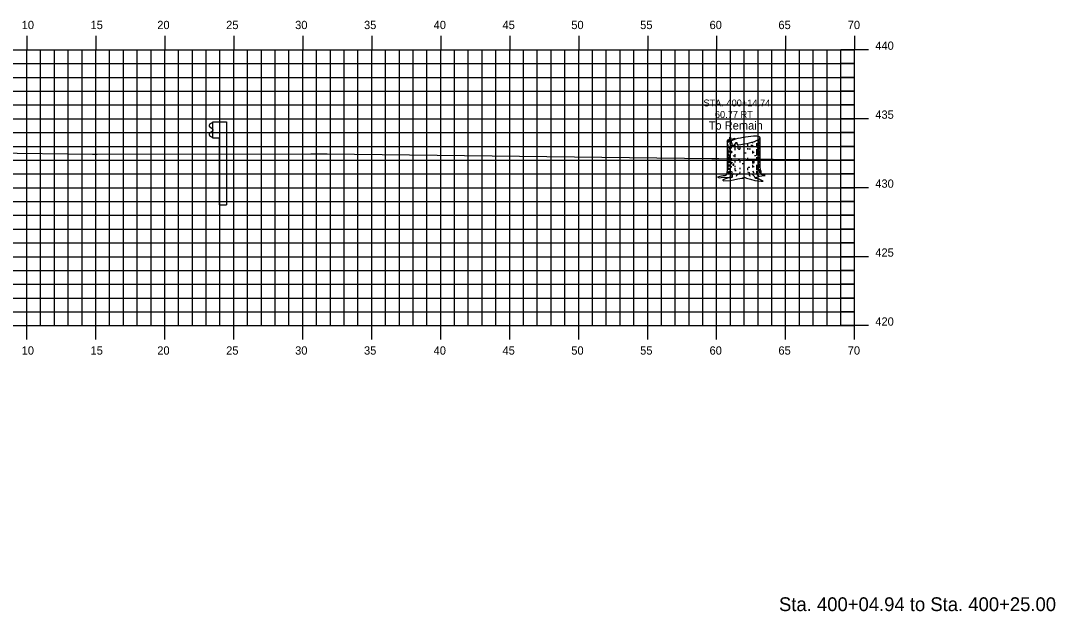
# Model space of a CAD drawing. Extents: x -161 to 764, y 111 to 210.
# Drawn here: x -78.3 to -3.3, y 113.1 to 155.9 of the extents above; entities that cross this region are included whole.
import ezdxf

# ---------------------------------------------------------------- set-up
doc = ezdxf.new("R2010")
doc.units = 0
for name, color, linetype in [('D_Text_Monospaced', 7, 'Continuous'), ('D_Text_Standard', 7, 'Continuous'), ('H_V ANNOTATION', 7, 'Continuous'), ('MAJOR', 7, 'Continuous'), ('MINOR', 7, 'Continuous'), ('S_Guardrail_Beam', 7, 'Continuous'), ('S_Roadway_Centerline', 7, 'Continuous'), ('S_Trees_Decid_Pay', 7, 'Continuous')]:
    doc.layers.add(name, color=color, linetype=linetype)

msp = doc.modelspace()

# ---------------------------------------------------------------- linework, layer by layer
at = {"layer": 'MAJOR'}
for p, q in [((-77.863, 154.77), (-77.863, 153.768)), ((-72.863, 154.77), (-72.863, 153.768)), ((-67.863, 154.77), (-67.863, 153.768)), ((-62.863, 154.77), (-62.863, 153.768)), ((-57.863, 154.77), (-57.863, 153.768)), ((-52.863, 154.77), (-52.863, 153.768)), ((-47.863, 154.77), (-47.863, 153.768)), ((-42.863, 154.77), (-42.863, 153.768)), ((-37.863, 154.77), (-37.863, 153.768)), ((-32.863, 154.77), (-32.863, 153.768)), ((-27.863, 154.77), (-27.863, 153.768)), ((-22.863, 154.77), (-22.863, 153.768)), ((-17.863, 154.77), (-17.863, 153.768)), ((-157.863, 153.768), (-17.863, 153.768)), ((-157.863, 153.768), (-17.863, 153.768)), ((-77.863, 133.768), (-77.863, 153.768)), ((-72.863, 133.768), (-72.863, 153.768)), ((-67.863, 133.768), (-67.863, 153.768)), ((-62.863, 133.768), (-62.863, 153.768)), ((-57.863, 133.768), (-57.863, 153.768)), ((-52.863, 133.768), (-52.863, 153.768)), ((-47.863, 133.768), (-47.863, 153.768)), ((-42.863, 133.768), (-42.863, 153.768)), ((-37.863, 133.768), (-37.863, 153.768)), ((-32.863, 133.768), (-32.863, 153.768)), ((-27.863, 133.768), (-27.863, 153.768)), ((-22.863, 133.768), (-22.863, 153.768)), ((-16.861, 153.768), (-18.865, 153.768)), ((-17.863, 133.768), (-17.863, 153.768)), ((-17.863, 133.768), (-17.863, 153.768)), ((-157.863, 148.768), (-17.863, 148.768)), ((-16.861, 148.768), (-18.865, 148.768)), ((-157.863, 143.768), (-17.863, 143.768)), ((-16.861, 143.768), (-18.865, 143.768)), ((-157.863, 138.768), (-17.863, 138.768)), ((-16.861, 138.768), (-18.865, 138.768)), ((-157.863, 133.768), (-17.863, 133.768)), ((-157.863, 133.768), (-17.863, 133.768)), ((-77.863, 132.766), (-77.863, 133.768)), ((-72.863, 132.766), (-72.863, 133.768)), ((-67.863, 132.766), (-67.863, 133.768)), ((-62.863, 132.766), (-62.863, 133.768)), ((-57.863, 132.766), (-57.863, 133.768)), ((-52.863, 132.766), (-52.863, 133.768)), ((-47.863, 132.766), (-47.863, 133.768)), ((-42.863, 132.766), (-42.863, 133.768)), ((-37.863, 132.766), (-37.863, 133.768)), ((-32.863, 132.766), (-32.863, 133.768)), ((-27.863, 132.766), (-27.863, 133.768)), ((-22.863, 132.766), (-22.863, 133.768)), ((-16.861, 133.768), (-18.865, 133.768)), ((-17.863, 132.766), (-17.863, 133.768))]:
    msp.add_line(p, q, dxfattribs=at)
at = {"layer": 'MINOR'}
for p, q in [((-76.863, 133.768), (-76.863, 153.768)), ((-75.863, 133.768), (-75.863, 153.768)), ((-74.863, 133.768), (-74.863, 153.768)), ((-73.863, 133.768), (-73.863, 153.768)), ((-71.863, 133.768), (-71.863, 153.768)), ((-70.863, 133.768), (-70.863, 153.768)), ((-69.863, 133.768), (-69.863, 153.768)), ((-68.863, 133.768), (-68.863, 153.768)), ((-66.863, 133.768), (-66.863, 153.768)), ((-65.863, 133.768), (-65.863, 153.768)), ((-64.863, 133.768), (-64.863, 153.768)), ((-63.863, 133.768), (-63.863, 153.768)), ((-61.863, 133.768), (-61.863, 153.768)), ((-60.863, 133.768), (-60.863, 153.768)), ((-59.863, 133.768), (-59.863, 153.768)), ((-58.863, 133.768), (-58.863, 153.768)), ((-56.863, 133.768), (-56.863, 153.768)), ((-55.863, 133.768), (-55.863, 153.768)), ((-54.863, 133.768), (-54.863, 153.768)), ((-53.863, 133.768), (-53.863, 153.768)), ((-51.863, 133.768), (-51.863, 153.768)), ((-50.863, 133.768), (-50.863, 153.768)), ((-49.863, 133.768), (-49.863, 153.768)), ((-48.863, 133.768), (-48.863, 153.768)), ((-46.863, 133.768), (-46.863, 153.768)), ((-45.863, 133.768), (-45.863, 153.768)), ((-44.863, 133.768), (-44.863, 153.768)), ((-43.863, 133.768), (-43.863, 153.768)), ((-41.863, 133.768), (-41.863, 153.768)), ((-40.863, 133.768), (-40.863, 153.768)), ((-39.863, 133.768), (-39.863, 153.768)), ((-38.863, 133.768), (-38.863, 153.768)), ((-36.863, 133.768), (-36.863, 153.768)), ((-35.863, 133.768), (-35.863, 153.768)), ((-34.863, 133.768), (-34.863, 153.768)), ((-33.863, 133.768), (-33.863, 153.768)), ((-31.863, 133.768), (-31.863, 153.768)), ((-30.863, 133.768), (-30.863, 153.768)), ((-29.863, 133.768), (-29.863, 153.768)), ((-28.863, 133.768), (-28.863, 153.768)), ((-26.863, 133.768), (-26.863, 153.768)), ((-25.863, 133.768), (-25.863, 153.768)), ((-24.863, 133.768), (-24.863, 153.768)), ((-23.863, 133.768), (-23.863, 153.768)), ((-21.863, 133.768), (-21.863, 153.768)), ((-20.863, 133.768), (-20.863, 153.768)), ((-19.863, 133.768), (-19.863, 153.768)), ((-18.863, 133.768), (-18.863, 153.768)), ((-157.863, 152.768), (-17.863, 152.768)), ((-17.863, 152.768), (-18.865, 152.768)), ((-157.863, 151.768), (-17.863, 151.768)), ((-17.863, 151.768), (-18.865, 151.768)), ((-157.863, 150.768), (-17.863, 150.768)), ((-17.863, 150.768), (-18.865, 150.768)), ((-157.863, 149.768), (-17.863, 149.768)), ((-17.863, 149.768), (-18.865, 149.768)), ((-157.863, 147.768), (-17.863, 147.768)), ((-17.863, 147.768), (-18.865, 147.768)), ((-157.863, 146.768), (-17.863, 146.768)), ((-17.863, 146.768), (-18.865, 146.768)), ((-157.863, 145.768), (-17.863, 145.768)), ((-17.863, 145.768), (-18.865, 145.768)), ((-157.863, 144.768), (-17.863, 144.768)), ((-17.863, 144.768), (-18.865, 144.768)), ((-157.863, 142.768), (-17.863, 142.768)), ((-17.863, 142.768), (-18.865, 142.768)), ((-157.863, 141.768), (-17.863, 141.768)), ((-17.863, 141.768), (-18.865, 141.768)), ((-157.863, 140.768), (-17.863, 140.768)), ((-17.863, 140.768), (-18.865, 140.768)), ((-157.863, 139.768), (-17.863, 139.768)), ((-17.863, 139.768), (-18.865, 139.768)), ((-157.863, 137.768), (-17.863, 137.768)), ((-17.863, 137.768), (-18.865, 137.768)), ((-157.863, 136.768), (-17.863, 136.768)), ((-17.863, 136.768), (-18.865, 136.768)), ((-157.863, 135.768), (-17.863, 135.768)), ((-17.863, 135.768), (-18.865, 135.768)), ((-157.863, 134.768), (-17.863, 134.768)), ((-17.863, 134.768), (-18.865, 134.768))]:
    msp.add_line(p, q, dxfattribs=at)
at = {"layer": 'S_Guardrail_Beam'}
for p, q in [((-64.38, 148.534), (-63.891, 148.534)), ((-64.38, 147.368), (-64.38, 148.534)), ((-63.891, 148.534), (-63.399, 148.534)), ((-63.891, 148.534), (-63.891, 147.368)), ((-63.399, 148.534), (-63.399, 142.534)), ((-64.479, 148.44), (-64.622, 148.34)), ((-64.622, 148.197), (-64.427, 148.061)), ((-64.427, 147.841), (-64.622, 147.705)), ((-64.38, 148.462), (-64.462, 148.447)), ((-64.393, 147.997), (-64.393, 147.906)), ((-64.622, 147.562), (-64.479, 147.462)), ((-64.462, 147.455), (-64.38, 147.441)), ((-63.891, 147.368), (-64.38, 147.368)), ((-63.891, 142.534), (-63.891, 147.368)), ((-63.891, 142.534), (-63.399, 142.534))]:
    msp.add_line(p, q, dxfattribs=at)
for centre, major_axis, start_param, end_param in [((-64.572, 148.269), (-0.0877, 0), 5.323254, 7.243116), ((-64.455, 148.406), (-0.0417, 0), 4.886922, 5.323254), ((-64.472, 147.997), (0.0789, 0), 0, 0.959931), ((-64.472, 147.906), (0.0789, 0), 5.323254, 6.283185), ((-64.572, 147.633), (-0.0877, 0), 5.323254, 7.243116), ((-64.455, 147.496), (-0.0417, 0), 0.959931, 1.396263)]:
    msp.add_ellipse(centre, major_axis=major_axis, ratio=0.995501, start_param=start_param, end_param=end_param, dxfattribs=at)
at = {"layer": 'S_Roadway_Centerline'}
msp.add_lwpolyline([(-80.412, 146.295), (-73.107, 146.205), (-72.997, 146.194), (-72.768, 146.204), (-57.278, 146.215), (-56.524, 146.221), (-56.324, 146.222), (-56.096, 146.218), (-28.215, 145.898), (-27.887, 145.887), (-27.711, 145.882), (-17.863, 145.764)], dxfattribs=at)
at = {"layer": 'S_Trees_Decid_Pay'}
for p, q in [((-26.896, 147.097), (-26.896, 146.923)), ((-25.639, 146.988), (-25.639, 146.708)), ((-25.256, 147.09), (-25.256, 147.003)), ((-24.983, 147.003), (-24.983, 146.811)), ((-24.851, 147.256), (-24.851, 147.003)), ((-24.771, 147.301), (-24.771, 147.18)), ((-24.771, 147.128), (-24.771, 146.914)), ((-27.045, 146.897), (-27.045, 146.643)), ((-27.045, 146.546), (-27.045, 146.076)), ((-26.959, 146.752), (-26.959, 146.54)), ((-26.959, 146.474), (-26.959, 146.326)), ((-26.811, 146.849), (-26.811, 146.644)), ((-26.811, 146.437), (-26.811, 146.282)), ((-26.55, 146.851), (-26.55, 146.731)), ((-26.55, 146.679), (-26.55, 146.494)), ((-26.312, 146.579), (-26.306, 146.686)), ((-26.185, 146.752), (-26.185, 146.572)), ((-25.639, 146.643), (-25.639, 146.54)), ((-25.256, 146.862), (-25.256, 146.723)), ((-25.256, 146.437), (-25.256, 146.245)), ((-24.983, 146.56), (-24.983, 146.282)), ((-24.851, 146.906), (-24.851, 146.643)), ((-24.851, 146.546), (-24.851, 146.237)), ((-24.771, 146.869), (-24.771, 146.531)), ((-24.771, 146.414), (-24.771, 146.053)), ((-27.045, 146.025), (-27.045, 145.891)), ((-27.045, 145.834), (-27.045, 145.508)), ((-26.959, 146.149), (-26.959, 145.848)), ((-26.959, 145.811), (-26.959, 145.568)), ((-26.811, 145.92), (-26.811, 145.7)), ((-26.811, 145.6), (-26.811, 145.479)), ((-26.55, 146.208), (-26.55, 145.98)), ((-26.55, 145.782), (-26.55, 145.597)), ((-26.185, 145.794), (-26.185, 145.597)), ((-25.639, 145.928), (-25.639, 145.708)), ((-25.256, 145.765), (-25.256, 145.557)), ((-24.983, 146.237), (-24.983, 146.128)), ((-24.983, 145.994), (-24.983, 145.765)), ((-24.851, 146.149), (-24.851, 146.082)), ((-24.851, 145.848), (-24.851, 145.751)), ((-24.851, 145.7), (-24.851, 145.34)), ((-24.771, 146.017), (-24.771, 145.568)), ((-24.771, 145.502), (-24.771, 145.22)), ((-27.042, 144.956), (-27.056, 144.839)), ((-27.045, 145.479), (-27.045, 145.059)), ((-26.959, 145.457), (-26.959, 145.317)), ((-26.959, 145.185), (-26.959, 145.029)), ((-26.811, 145.328), (-26.811, 145.23)), ((-26.55, 145.362), (-26.55, 145.285)), ((-26.55, 145.208), (-26.55, 145.034)), ((-26.185, 145.214), (-26.185, 145.111)), ((-25.639, 145.208), (-25.639, 145.034)), ((-25.26, 144.979), (-25.18, 144.847)), ((-25.256, 145.436), (-25.256, 145.237)), ((-24.983, 145.436), (-24.983, 145.053)), ((-24.851, 145.288), (-24.851, 145.121))]:
    msp.add_line(p, q, dxfattribs=at)
for points in [[(-27.096, 147.172), (-27.096, 145.034), (-27.116, 144.893), (-27.122, 144.767), (-27.165, 144.68), (-27.258, 144.631), (-27.394, 144.631), (-27.637, 144.575), (-27.804, 144.526), (-27.661, 144.495), (-27.424, 144.532), (-27.214, 144.52), (-26.953, 144.526), (-26.829, 144.544), (-26.799, 144.502), (-26.737, 144.544), (-26.836, 144.477), (-27.071, 144.452), (-27.301, 144.39), (-27.431, 144.32), (-27.332, 144.277), (-26.91, 144.296), (-26.632, 144.339), (-26.333, 144.415), (-26.047, 144.452), (-25.942, 144.452), (-25.924, 144.532), (-25.855, 144.538), (-25.689, 144.452), (-25.403, 144.396), (-25.104, 144.289), (-24.645, 144.24), (-24.491, 144.252), (-24.833, 144.403), (-25.036, 144.433), (-25.024, 144.508), (-24.764, 144.607), (-24.589, 144.637), (-24.348, 144.649), (-24.546, 144.687), (-24.608, 144.723), (-24.632, 144.81), (-24.645, 144.979), (-24.69, 145.065), (-24.718, 145.306), (-24.718, 147.392)], [(-26.739, 146.844), (-26.747, 146.988), (-26.792, 146.981), (-26.807, 147.355), (-26.901, 147.363), (-26.916, 147.443), (-26.953, 147.106), (-26.999, 147.2), (-27.019, 147.046), (-27.096, 147.172), (-27.09, 146.982)], [(-27.096, 147.172), (-27.05, 147.195), (-27.027, 147.26), (-26.976, 147.283), (-26.942, 147.208)], [(-26.717, 147.21), (-26.696, 147.318), (-26.564, 147.349), (-26.557, 147.261)], [(-26.578, 146.849), (-26.541, 146.952), (-26.476, 146.958), (-26.476, 147.04), (-26.401, 147.046), (-26.376, 146.866)], [(-26.688, 145.479), (-26.696, 145.405), (-26.622, 145.399), (-26.607, 145.516)], [(-25.142, 145.571), (-25.144, 145.648), (-25.151, 145.714)], [(-26.976, 144.964), (-26.982, 144.839), (-27.064, 144.744)], [(-26.829, 144.544), (-26.811, 144.723), (-26.749, 144.86), (-26.756, 144.96)], [(-26.638, 144.792), (-26.712, 144.723), (-26.731, 144.625), (-26.737, 144.544)], [(-26.187, 144.927), (-26.204, 144.773), (-26.401, 144.693), (-26.447, 144.59)], [(-25.621, 144.919), (-25.518, 144.868), (-25.504, 144.662), (-25.401, 144.633)], [(-24.966, 144.993), (-24.966, 144.788), (-24.909, 144.678), (-24.812, 144.662)], [(-24.826, 145.067), (-24.754, 144.964), (-24.754, 144.839)], [(-24.769, 145.148), (-24.709, 144.987), (-24.695, 144.862), (-24.703, 144.765)], [(-25.036, 144.433), (-25.123, 144.575), (-25.254, 144.717)]]:
    msp.add_lwpolyline(points, dxfattribs=at)
for centre, radius, start, end in [((-26.286, 145.984), 1.299, 107.86134, 113.3069), ((-24.806, 141.391), 6.126, 100.77788, 107.86134), ((-24.806, 141.391), 6.126, 93.69441, 100.77788), ((-27.008, 152.959), 6.126, 280.77788, 287.86134), ((-25.117, 146.207), 1.299, 78.27788, 93.69441), ((-25.528, 148.365), 1.299, 287.86134, 303.27788), ((-24.95, 147.01), 0.48, 69.98432, 78.27788), ((-25.078, 147.68), 0.48, 303.27788, 311.57144), ((-24.842, 147.306), 0.164, 55.77788, 69.98432), ((-24.858, 147.135), 0.166, 301.67004, 315), ((-24.868, 147.444), 0.164, 311.57144, 325.77788), ((-24.81, 147.353), 0.107, 45.9547, 55.77788), ((-24.817, 147.095), 0.109, 315, 324.82628), ((-24.78, 147.384), 0.0645, 33.27788, 45.9547), ((-24.821, 147.412), 0.107, 325.77788, 335.60106), ((-24.782, 147.07), 0.0657, 324.82628, 337.5), ((-24.772, 147.389), 0.0544, 22.46002, 33.27788), ((-24.782, 147.394), 0.0645, 335.60106, 348.27788), ((-24.765, 147.392), 0.0467, 10.77788, 22.46002), ((-24.772, 147.066), 0.0554, 337.5, 348.31854), ((-24.765, 147.392), 0.0467, 359.09574, 10.77788), ((-24.773, 147.392), 0.0544, 348.27788, 359.09574), ((-27.048, 146.803), 0.0476, 180, 191.68146), ((-27.048, 146.282), 0.0476, 180, 191.68146), ((-27.04, 146.805), 0.0554, 191.68146, 202.5), ((-27.04, 146.284), 0.0554, 191.68146, 202.5), ((-27.031, 146.809), 0.0657, 202.5, 215.17372), ((-27.031, 146.288), 0.0657, 202.5, 215.17372), ((-26.995, 146.834), 0.109, 215.17372, 225), ((-26.995, 146.313), 0.109, 215.17372, 225), ((-26.955, 146.874), 0.166, 225, 239.19244), ((-26.955, 146.611), 0.166, 237.03779, 239.19244), ((-26.792, 146.884), 0.484, 239.19244, 247.5), ((-26.483, 147.63), 1.292, 247.5, 248.35373), ((-26.483, 147.894), 1.292, 250.61187, 255.28558), ((-26.483, 147.63), 1.292, 255.28558, 259.26323), ((-26.697, 148.143), 1.299, 268.12894, 273.69441), ((-27.008, 152.959), 6.126, 273.69441, 274.02462), ((-27.008, 152.959), 6.126, 275.91473, 280.77788), ((-25.907, 152.481), 5.916, 266.07764, 267.30434), ((-25.907, 152.218), 5.916, 270.1162, 271.77083), ((-25.907, 152.481), 5.916, 273.53821, 274.89239), ((-25.906, 152.742), 5.916, 274.95145, 276.30875), ((-25.907, 152.218), 5.916, 276.31835, 277.15463), ((-25.331, 147.63), 1.292, 277.15463, 278.36619), ((-25.33, 148.154), 1.292, 285.56513, 289.09156), ((-25.331, 147.894), 1.292, 288.08294, 292.5), ((-25.331, 147.63), 1.292, 291.8071, 292.5), ((-25.022, 146.884), 0.484, 292.5, 300.80756), ((-25.022, 147.147), 0.484, 297.41617, 300.80756), ((-24.859, 146.874), 0.166, 300.80756, 315), ((-24.859, 146.611), 0.166, 300.80756, 301.6001), ((-24.818, 146.834), 0.109, 315, 324.82628), ((-24.818, 146.313), 0.109, 315, 324.82628), ((-24.783, 146.809), 0.0657, 324.82628, 337.5), ((-24.783, 146.288), 0.0657, 324.82628, 337.5), ((-24.773, 146.805), 0.0554, 337.5, 348.31854), ((-24.773, 146.284), 0.0554, 337.5, 348.31854), ((-27.048, 146.025), 0.0476, 180, 191.68146), ((-27.048, 145.759), 0.0476, 180, 191.68146), ((-27.04, 146.026), 0.0554, 191.68146, 202.5), ((-27.04, 145.761), 0.0554, 191.68146, 202.5), ((-27.031, 146.03), 0.0657, 202.5, 215.17372), ((-27.031, 145.765), 0.0657, 202.5, 215.17372), ((-26.995, 146.055), 0.109, 215.17372, 225), ((-26.995, 145.79), 0.109, 215.17372, 225), ((-26.955, 146.353), 0.166, 225, 239.19244), ((-26.955, 146.096), 0.166, 225, 239.19244), ((-26.955, 145.83), 0.166, 225, 239.19244), ((-26.792, 146.626), 0.484, 239.19244, 245.77245), ((-26.792, 146.103), 0.484, 239.19244, 247.5), ((-26.483, 147.373), 1.292, 247.5, 248.48417), ((-26.483, 147.115), 1.292, 247.5, 251.79898), ((-26.483, 146.85), 1.292, 247.5, 248.35373), ((-26.483, 146.85), 1.292, 255.28558, 259.24628), ((-26.483, 147.373), 1.292, 261.87258, 262.84538), ((-25.907, 151.961), 5.916, 262.84538, 263.7595), ((-25.907, 151.703), 5.916, 266.27211, 267.30434), ((-25.907, 151.438), 5.916, 268.92065, 270), ((-25.907, 151.438), 5.916, 270, 270.27568), ((-25.907, 151.438), 5.916, 276.31835, 277.15463), ((-25.331, 146.85), 1.292, 277.15463, 278.37952), ((-25.331, 147.373), 1.292, 279.25654, 285.6105), ((-25.331, 147.115), 1.292, 285.61049, 290.10015), ((-25.022, 146.103), 0.484, 292.5, 300.80756), ((-25.022, 146.626), 0.484, 294.63721, 300.80756), ((-24.859, 146.353), 0.166, 300.80756, 315), ((-24.859, 145.83), 0.166, 300.80756, 302.06939), ((-24.859, 146.096), 0.166, 302.06939, 315), ((-24.818, 146.055), 0.109, 315, 324.82628), ((-24.783, 146.03), 0.0657, 324.82628, 337.5), ((-24.773, 146.026), 0.0554, 337.5, 348.31854), ((-24.773, 145.761), 0.0554, 337.5, 348.31854), ((-27.048, 145.23), 0.0476, 180, 191.68146), ((-27.04, 145.232), 0.0554, 191.68146, 202.5), ((-27.031, 145.236), 0.0657, 202.5, 215.17372), ((-26.995, 145.261), 0.109, 215.17372, 225), ((-26.955, 145.301), 0.166, 225, 239.19244), ((-26.792, 145.574), 0.484, 239.19244, 247.5), ((-26.792, 145.832), 0.484, 242.73401, 247.5), ((-26.483, 146.32), 1.292, 247.5, 248.35373), ((-26.483, 146.578), 1.292, 251.36642, 255.28558), ((-25.907, 150.908), 5.916, 263.78314, 264.76555), ((-25.907, 151.166), 5.916, 273.26366, 274.46102), ((-25.907, 151.166), 5.916, 276.31835, 277.15463), ((-25.331, 146.578), 1.292, 277.15463, 278.36619), ((-25.331, 146.578), 1.292, 285.61049, 289.15336), ((-25.322, 146.324), 1.292, 291.36963, 292.0604), ((-25.022, 145.574), 0.484, 292.5, 296.54993), ((-24.859, 145.559), 0.166, 302.06939, 315), ((-24.818, 145.518), 0.109, 315, 324.82628), ((-24.783, 145.493), 0.0657, 324.82628, 337.5), ((-24.773, 145.489), 0.0554, 337.5, 348.31854)]:
    msp.add_arc(centre, radius, start, end, dxfattribs=at)

# ---------------------------------------------------------------- texts
at = {"layer": 'D_Text_Monospaced'}
for s, height, p in [('STA. 400+14.74', 0.49998, (-28.824, 149.661)), ('60.77 RT', 0.5, (-27.991, 148.827))]:
    msp.add_text(s, height=height, dxfattribs=at).set_placement(p)
at = {"layer": 'D_Text_Standard'}
msp.add_text('To Remain', height=0.6, dxfattribs=at).set_placement((-28.441, 147.984))
at = {"layer": 'H_V ANNOTATION'}
for s, p in [('10', (-78.238, 155.268)), ('15', (-73.246, 155.268)), ('20', (-68.409, 155.268)), ('25', (-63.417, 155.268)), ('30', (-58.415, 155.268)), ('35', (-53.423, 155.268)), ('40', (-48.377, 155.268)), ('45', (-43.385, 155.268)), ('50', (-38.399, 155.268)), ('55', (-33.407, 155.268)), ('60', (-28.377, 155.268)), ('65', (-23.385, 155.268)), ('70', (-18.361, 155.268)), ('440', (-16.363, 153.768)), ('435', (-16.363, 148.768)), ('430', (-16.363, 143.768)), ('425', (-16.363, 138.768)), ('420', (-16.363, 133.768)), ('10', (-78.238, 131.668)), ('15', (-73.246, 131.668)), ('20', (-68.409, 131.668)), ('25', (-63.417, 131.668)), ('30', (-58.415, 131.668)), ('35', (-53.423, 131.668)), ('40', (-48.377, 131.668)), ('45', (-43.385, 131.668)), ('50', (-38.399, 131.668)), ('55', (-33.407, 131.668)), ('60', (-28.377, 131.668)), ('65', (-23.385, 131.668)), ('70', (-18.361, 131.668))]:
    msp.add_text(s, height=0.6, dxfattribs=at).set_placement(p)
msp.add_text('Sta. 400+04.94 to Sta. 400+25.00', height=1.0002, rotation=360, dxfattribs=at).set_placement((-23.343, 113.074))

doc.saveas('drawing.dxf')
